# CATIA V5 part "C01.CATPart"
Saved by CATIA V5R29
Part number: C01
Source: Unknown
Bounding box of the stored display mesh (mm): x -30 to 30, y -40 to 40, z -30 to 230
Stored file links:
  C:\Users\Administrator\Desktop\프로젝트\Boxfold\TapeCutter\C01.CATPart
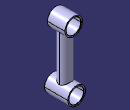
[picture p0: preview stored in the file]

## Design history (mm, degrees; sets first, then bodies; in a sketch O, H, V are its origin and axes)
Body1 (main body)
  Solid1 "PartBody": solid without history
